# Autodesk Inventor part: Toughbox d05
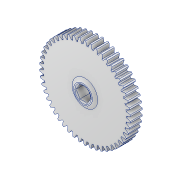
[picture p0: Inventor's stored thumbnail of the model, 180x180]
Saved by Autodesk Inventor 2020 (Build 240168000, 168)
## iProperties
Created: 2020-01
Part Number: Toughbox d05
Material: Aluminum 6061
Document SubType Name: Modeling
Designer: woodk
Density: 2.7 g/cm^3
Appearance: Aluminum - Flat
Vendor: KoP
Mass: 73.133 g
Surface Area: 100.096 cm^2
Volume: 27.0863 cm^3
Author: woodk
Revision Number: ANY
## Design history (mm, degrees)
feature "Imported1"
body "Solid1"
